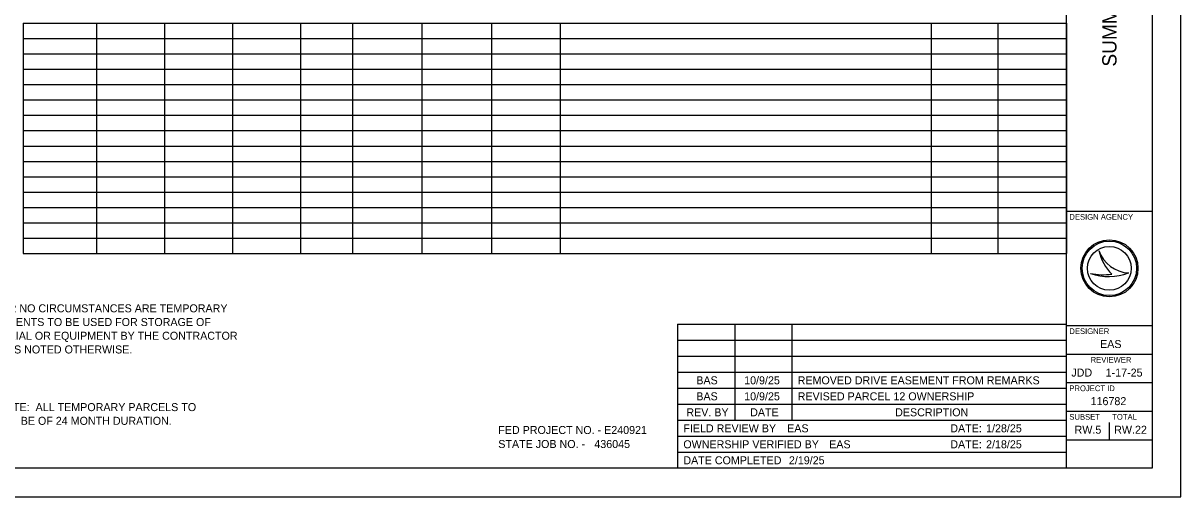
# Model space of a CAD drawing. Extents: x 0 to 34, y 0 to 22.
# Drawn here: x 13.75 to 34, y 0 to 8.29 of the extents above; entities that cross this region are included whole.
import ezdxf

# ---------------------------------------------------------------- set-up
doc = ezdxf.new("R2010")
doc.units = 0
for name, color, linetype in [('Default', 7, 'Continuous'), ('SH_Border', 7, 'Continuous'), ('SH_Cut_Line', 7, 'Continuous'), ('SH_Data', 7, 'Continuous'), ('SH_Text', 7, 'Continuous')]:
    doc.layers.add(name, color=color, linetype=linetype)

msp = doc.modelspace()

# ---------------------------------------------------------------- linework, layer by layer
at = {"layer": 'Default'}
for p, q in [((13.749, 8.291), (16.219, 8.291)), ((13.749, 8.291), (13.749, 8.023)), ((15.029, 8.291), (15.029, 8.023)), ((16.219, 8.291), (30.797, 8.291)), ((16.219, 8.291), (16.219, 8.023)), ((17.409, 8.291), (17.409, 8.023)), ((18.599, 8.291), (18.599, 8.023)), ((19.508, 8.291), (19.508, 8.023)), ((20.724, 8.291), (20.724, 8.023)), ((21.94, 8.291), (21.94, 8.023)), ((23.143, 8.291), (23.143, 8.023)), ((29.632, 8.291), (29.632, 8.023)), ((30.797, 8.291), (32, 8.291)), ((30.797, 8.291), (30.797, 8.023)), ((32, 8.291), (32, 8.023)), ((13.749, 8.023), (16.219, 8.023)), ((13.749, 8.023), (13.749, 7.754)), ((15.029, 8.023), (15.029, 7.754)), ((16.219, 8.023), (30.797, 8.023)), ((16.219, 8.023), (16.219, 7.754)), ((17.409, 8.023), (17.409, 7.754)), ((18.599, 8.023), (18.599, 7.754)), ((19.508, 8.023), (19.508, 7.754)), ((20.724, 8.023), (20.724, 7.754)), ((21.94, 8.023), (21.94, 7.754)), ((23.143, 8.023), (23.143, 7.754)), ((29.632, 8.023), (29.632, 7.754)), ((30.797, 8.023), (32, 8.023)), ((30.797, 8.023), (30.797, 7.754)), ((32, 8.023), (32, 7.754)), ((13.749, 7.754), (16.219, 7.754)), ((13.749, 7.754), (13.749, 6.948)), ((15.029, 7.754), (15.029, 6.948)), ((16.219, 7.754), (30.797, 7.754)), ((16.219, 7.754), (16.219, 6.948)), ((17.409, 7.754), (17.409, 6.948)), ((18.599, 7.754), (18.599, 6.948)), ((19.508, 7.754), (19.508, 6.948)), ((20.724, 7.754), (20.724, 6.948)), ((21.94, 7.754), (21.94, 6.948)), ((23.143, 7.754), (23.143, 6.948)), ((29.632, 7.754), (29.632, 6.948)), ((30.797, 7.754), (32, 7.754)), ((30.797, 7.754), (30.797, 6.948)), ((32, 7.754), (32, 6.948)), ((13.749, 7.485), (16.219, 7.485)), ((16.219, 7.485), (30.797, 7.485)), ((30.797, 7.485), (32, 7.485)), ((13.749, 7.216), (16.219, 7.216)), ((16.219, 7.216), (30.797, 7.216)), ((30.797, 7.216), (32, 7.216)), ((13.749, 6.948), (16.219, 6.948)), ((13.749, 6.948), (13.749, 6.679)), ((15.029, 6.948), (15.029, 6.679)), ((16.219, 6.948), (30.797, 6.948)), ((16.219, 6.948), (16.219, 6.679)), ((17.409, 6.948), (17.409, 6.679)), ((18.599, 6.948), (18.599, 6.679)), ((19.508, 6.948), (19.508, 6.679)), ((20.724, 6.948), (20.724, 6.679)), ((21.94, 6.948), (21.94, 6.679)), ((23.143, 6.948), (23.143, 6.679)), ((29.632, 6.948), (29.632, 6.679)), ((30.797, 6.948), (32, 6.948)), ((30.797, 6.948), (30.797, 6.679)), ((32, 6.948), (32, 6.679)), ((13.749, 6.679), (16.219, 6.679)), ((13.749, 6.679), (13.749, 4.26)), ((15.029, 6.679), (15.029, 4.26)), ((16.219, 6.679), (30.797, 6.679)), ((16.219, 6.679), (16.219, 4.26)), ((17.409, 6.679), (17.409, 4.26)), ((18.599, 6.679), (18.599, 4.26)), ((19.508, 6.679), (19.508, 4.26)), ((20.724, 6.679), (20.724, 4.26)), ((21.94, 6.679), (21.94, 4.26)), ((23.143, 6.679), (23.143, 4.26)), ((29.632, 6.679), (29.632, 4.26)), ((30.797, 6.679), (32, 6.679)), ((30.797, 6.679), (30.797, 4.26)), ((32, 6.679), (32, 4.26)), ((13.749, 6.41), (16.219, 6.41)), ((16.219, 6.41), (30.797, 6.41)), ((30.797, 6.41), (32, 6.41)), ((13.749, 6.141), (16.219, 6.141)), ((16.219, 6.141), (30.797, 6.141)), ((30.797, 6.141), (32, 6.141)), ((13.749, 5.872), (16.219, 5.872)), ((16.219, 5.872), (30.797, 5.872)), ((30.797, 5.872), (32, 5.872)), ((13.749, 5.604), (16.219, 5.604)), ((16.219, 5.604), (30.797, 5.604)), ((30.797, 5.604), (32, 5.604)), ((13.749, 5.335), (16.219, 5.335)), ((16.219, 5.335), (30.797, 5.335)), ((30.797, 5.335), (32, 5.335)), ((13.749, 5.066), (16.219, 5.066)), ((16.219, 5.066), (30.797, 5.066)), ((30.797, 5.066), (32, 5.066)), ((13.749, 4.797), (16.219, 4.797)), ((16.219, 4.797), (30.797, 4.797)), ((30.797, 4.797), (32, 4.797)), ((13.749, 4.529), (16.219, 4.529)), ((16.219, 4.529), (30.797, 4.529)), ((30.797, 4.529), (32, 4.529)), ((13.749, 4.26), (16.219, 4.26)), ((16.219, 4.26), (30.797, 4.26)), ((30.797, 4.26), (32, 4.26))]:
    msp.add_line(p, q, dxfattribs=at)
at = {"layer": 'SH_Border'}
for p, q in [((32, 0.5), (32, 21.5)), ((32, 5), (33.5, 5)), ((32, 3), (33.5, 3)), ((32, 2.5), (33.5, 2.5)), ((32, 2), (33.5, 2)), ((32, 1.5), (33.5, 1.5)), ((32, 1), (33.5, 1))]:
    msp.add_line(p, q, dxfattribs=at)
msp.add_lwpolyline([(1.5, 21.5), (33.5, 21.5), (33.5, 0.5), (1.5, 0.5)], close=True, dxfattribs=at)
at = {"layer": 'SH_Cut_Line'}
msp.add_lwpolyline([(0, 0), (34, 0), (34, 22), (0, 22)], close=True, dxfattribs=at)
at = {"layer": 'SH_Data'}
for p, q in [((32.567, 4.31), (32.567, 4.31)), ((32.417, 3.91), (32.417, 3.91)), ((32.75, 4), (32.75, 4)), ((33.087, 3.919), (33.087, 3.919)), ((32.75, 1), (32.75, 1.3))]:
    msp.add_line(p, q, dxfattribs=at)
for radius in [0.5, 0.477, 0.477, 0.382]:
    msp.add_circle((32.75, 4), radius, dxfattribs=at)
for centre, radius, start, end in [((33.116, 4.498), 0.58, 198.9257, 198.9319), ((33.347, 4.47), 0.796, 191.6379, 191.6421), ((33.116, 4.498), 0.58, 198.9319, 267.1657), ((33.347, 4.47), 0.796, 191.6421, 226.0947), ((32.739, 4.87), 1.013, 251.4576, 290.0832), ((32.648, 5.154), 1.266, 259.4964, 259.4995), ((32.739, 4.87), 1.013, 251.4527, 251.4576), ((32.648, 5.154), 1.266, 259.4995, 276.6672)]:
    msp.add_arc(centre, radius, start, end, dxfattribs=at)
at = {"layer": 'SH_Text'}
for p, q in [((25.197, 3.02), (25.197, 0.5)), ((25.197, 3.02), (32, 3.02)), ((26.197, 3.02), (26.197, 1.34)), ((27.197, 3.02), (27.197, 1.34)), ((25.197, 2.74), (32, 2.74)), ((25.197, 2.46), (32, 2.46)), ((25.197, 2.18), (32, 2.18)), ((25.197, 1.9), (32, 1.9)), ((25.197, 1.62), (32, 1.62)), ((25.197, 1.34), (32, 1.34)), ((25.197, 1.06), (32, 1.06)), ((25.197, 0.78), (32, 0.78)), ((32, 0.5), (32, 0.5))]:
    msp.add_line(p, q, dxfattribs=at)

# ---------------------------------------------------------------- texts
at = {"layer": 'SH_Data'}
msp.add_text('SUMMARY OF ADDITIONAL RIGHT OF WAY - WAY-3-4.62', height=0.25, rotation=90, dxfattribs=at).set_placement((32.875, 7.531))
for s, height, p in [('DESIGN AGENCY', 0.1, (32.05, 4.85)), ('DESIGNER', 0.1, (32.05, 2.85)), ('EAS', 0.14, (32.587, 2.605)), ('REVIEWER', 0.1, (32.422, 2.35)), ('JDD', 0.14, (32.084, 2.105)), ('1-17-25', 0.14, (32.685, 2.105)), ('PROJECT ID', 0.1, (32.05, 1.85)), ('116782', 0.14, (32.421, 1.605)), ('SUBSET', 0.1, (32.05, 1.35)), ('TOTAL', 0.1, (32.8, 1.35)), ('RW.5', 0.14, (32.141, 1.105)), ('RW.22', 0.14, (32.834, 1.105))]:
    msp.add_text(s, height=height, dxfattribs=at).set_placement(p)
at = {"layer": 'SH_Text'}
for s, p in [('UNDER NO CIRCUMSTANCES ARE TEMPORARY', (12.965, 3.23)), ('EASEMENTS TO BE USED FOR STORAGE OF', (12.965, 2.99)), ('MATERIAL OR EQUIPMENT BY THE CONTRACTOR', (12.965, 2.75)), ('UNLESS NOTED OTHERWISE.', (12.965, 2.51)), ('BAS', (25.524, 1.97)), (' 10/9/25', (26.309, 1.97)), ('REMOVED DRIVE EASEMENT FROM REMARKS    ', (27.297, 1.97)), ('BAS', (25.524, 1.69)), (' 10/9/25', (26.309, 1.69)), ('REVISED PARCEL 12 OWNERSHIP            ', (27.297, 1.69)), ('NOTE:  ALL TEMPORARY PARCELS TO', (13.29, 1.501)), ('REV. BY', (25.35, 1.41)), ('DATE', (26.466, 1.41)), ('DESCRIPTION', (29.002, 1.41)), ('        BE OF 24 MONTH DURATION.', (13.29, 1.261)), ('FED PROJECT NO. - E240921', (22.06, 1.1)), ('FIELD REVIEW BY', (25.297, 1.13)), ('EAS                      ', (27.113, 1.13)), ('DATE:', (29.967, 1.13)), ('1/28/25 ', (30.593, 1.13)), ('STATE JOB NO. -', (22.06, 0.855)), ('436045', (23.74, 0.855)), ('OWNERSHIP VERIFIED BY', (25.297, 0.85)), ('EAS               ', (27.848, 0.85)), ('DATE:', (29.967, 0.85)), ('2/18/25 ', (30.593, 0.85)), ('DATE COMPLETED', (25.297, 0.57)), ('2/19/25                             ', (27.144, 0.57))]:
    msp.add_text(s, height=0.14, dxfattribs=at).set_placement(p)

doc.saveas('drawing.dxf')
